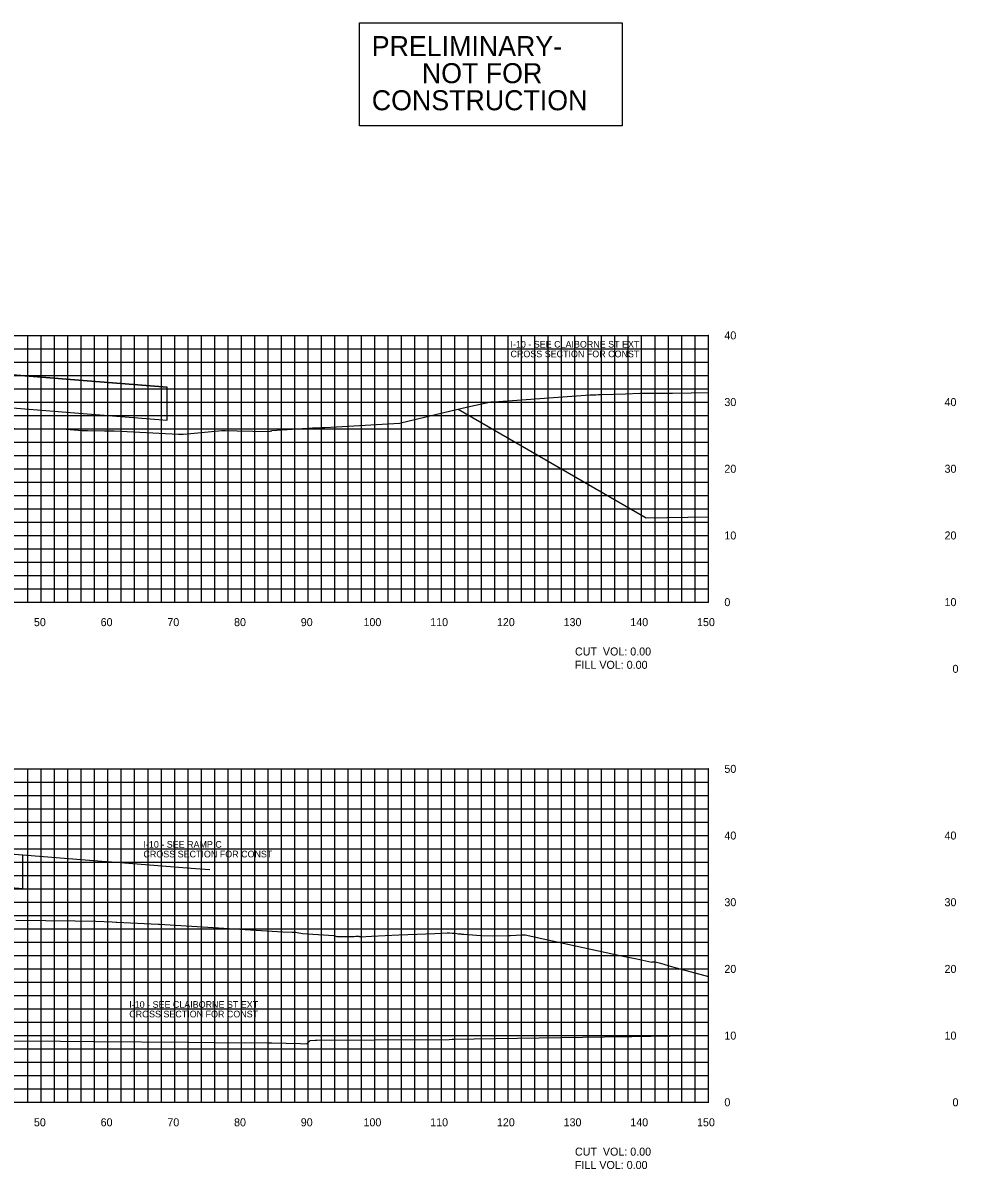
# Model space of a CAD drawing. Extents: x 1800880 to 1814006, y 250083 to 250560.
# Drawn here: x 1811858.3 to 1811998.4, y 250089.4 to 250261.3 of the extents above; entities that cross this region are included whole.
import ezdxf

# ---------------------------------------------------------------- set-up
doc = ezdxf.new("R2010")
doc.units = 0
for name, color, linetype in [('33', 7, 'Continuous'), ('AXIS', 7, 'Continuous'), ('CL-CNST', 7, 'Continuous'), ('DESIGN - DRAINAGE - Bridges', 7, 'Continuous'), ('DRAINAGETXT', 7, 'Continuous'), ('EPTEXT', 7, 'Continuous'), ('Level 32', 7, 'Continuous'), ('Level 46', 7, 'Continuous'), ('Level 62', 7, 'Continuous'), ('TOPO', 7, 'Continuous')]:
    doc.layers.add(name, color=color, linetype=linetype)

msp = doc.modelspace()

# ---------------------------------------------------------------- linework, layer by layer
at = {"layer": 'AXIS'}
msp.add_lwpolyline([(1811811, 250212.19), (1811812.25, 250212.09), (1811822.25, 250211.29), (1811834.25, 250210.33), (1811867.89, 250207.64), (1811879.89, 250206.68)], dxfattribs=at)
at = {"layer": 'CL-CNST'}
for points in [[(1811852.17, 250200.53), (1811861.88, 250200.43), (1811864.1, 250200.41), (1811865.35, 250200.32), (1811867.15, 250200.19), (1811867.94, 250200.18), (1811870.5, 250200.13), (1811871.44, 250200.11), (1811871.93, 250200.1), (1811881.59, 250199.61), (1811881.62, 250199.61), (1811881.77, 250199.6), (1811881.81, 250199.6), (1811881.93, 250199.6), (1811882.29, 250199.61), (1811883.41, 250199.71), (1811888.08, 250200.16), (1811888.14, 250200.16), (1811888.45, 250200.16), (1811888.61, 250200.16), (1811890.36, 250200.13), (1811895.05, 250200.03), (1811895.29, 250200.08), (1811895.41, 250200.11), (1811895.46, 250200.12), (1811895.49, 250200.13), (1811895.5, 250200.13), (1811895.52, 250200.14), (1811895.53, 250200.14), (1811895.53, 250200.14), (1811895.54, 250200.14), (1811895.54, 250200.14), (1811895.54, 250200.14), (1811895.55, 250200.14), (1811895.55, 250200.14), (1811895.55, 250200.14), (1811895.55, 250200.14), (1811895.56, 250200.14), (1811895.56, 250200.14), (1811895.56, 250200.14), (1811895.56, 250200.15), (1811895.56, 250200.15), (1811895.56, 250200.15), (1811901.65, 250200.55), (1811901.78, 250200.56), (1811901.79, 250200.56), (1811901.81, 250200.56), (1811901.84, 250200.56), (1811901.87, 250200.56), (1811901.91, 250200.57), (1811902.57, 250200.58), (1811902.79, 250200.59), (1811903.01, 250200.6), (1811903.49, 250200.63), (1811905.26, 250200.73), (1811914.69, 250201.27), (1811921.35, 250202.85), (1811924.94, 250203.7), (1811928.41, 250204.47), (1811928.86, 250204.47), (1811928.89, 250204.47), (1811943.29, 250205.52), (1811943.41, 250205.53), (1811943.6, 250205.54), (1811943.62, 250205.54), (1811943.98, 250205.54), (1811944.12, 250205.54), (1811944.54, 250205.55), (1811944.99, 250205.56), (1811948.59, 250205.68), (1811950.73, 250205.75), (1811951.53, 250205.76), (1811955.63, 250205.78), (1811958.4, 250205.81), (1811961, 250205.85)], [(1811857.17, 250126.75), (1811866.1, 250126.64), (1811869.16, 250126.61), (1811871.62, 250126.47), (1811872.21, 250126.44), (1811872.34, 250126.43), (1811878.53, 250126.13), (1811878.71, 250126.13), (1811897.2, 250125.01), (1811898.62, 250124.93), (1811898.66, 250124.93), (1811898.82, 250124.93), (1811899.17, 250124.92), (1811899.35, 250124.87), (1811900.18, 250124.73), (1811904.88, 250124.42), (1811905.31, 250124.3), (1811907.83, 250124.3), (1811907.9, 250124.3), (1811907.92, 250124.3), (1811908.14, 250124.35), (1811908.39, 250124.34), (1811908.4, 250124.34), (1811908.41, 250124.34), (1811908.42, 250124.34), (1811908.44, 250124.34), (1811908.46, 250124.34), (1811908.48, 250124.34), (1811908.53, 250124.33), (1811908.56, 250124.32), (1811908.6, 250124.32), (1811908.65, 250124.31), (1811908.72, 250124.29), (1811908.83, 250124.27), (1811908.85, 250124.26), (1811910.49, 250124.34), (1811914.6, 250124.52), (1811920.01, 250124.76), (1811921.83, 250124.82), (1811922.18, 250124.85), (1811922.59, 250124.81), (1811922.99, 250124.77), (1811923.28, 250124.74), (1811923.51, 250124.71), (1811923.69, 250124.69), (1811923.84, 250124.68), (1811923.96, 250124.67), (1811924.06, 250124.66), (1811924.15, 250124.65), (1811924.23, 250124.64), (1811924.29, 250124.63), (1811924.35, 250124.63), (1811925.66, 250124.54), (1811926.83, 250124.45), (1811928.68, 250124.38), (1811931.15, 250124.46), (1811931.32, 250124.45), (1811933.02, 250124.54), (1811933.35, 250124.53), (1811933.53, 250124.53), (1811936.51, 250123.89), (1811947.97, 250121.41), (1811948.48, 250121.3), (1811950.28, 250120.94), (1811952.54, 250120.46), (1811952.56, 250120.47), (1811953, 250120.47), (1811953.84, 250120.27), (1811955.13, 250119.9), (1811956.16, 250119.61), (1811961, 250118.3)]]:
    msp.add_lwpolyline(points, dxfattribs=at)
at = {"layer": 'DESIGN - DRAINAGE - Bridges'}
for p, q in [((1811961, 250174.43), (1811961, 250214.43)), ((1811961.06, 250214.43), (1811961, 250214.43)), ((1811961.06, 250204.43), (1811961, 250204.43)), ((1811961.06, 250194.43), (1811961, 250194.43)), ((1811961.06, 250184.43), (1811961, 250184.43)), ((1811661, 250174.43), (1811961, 250174.43)), ((1811861, 250174.37), (1811861, 250174.43)), ((1811871, 250174.37), (1811871, 250174.43)), ((1811881, 250174.37), (1811881, 250174.43)), ((1811891, 250174.37), (1811891, 250174.43)), ((1811901, 250174.37), (1811901, 250174.43)), ((1811911, 250174.37), (1811911, 250174.43)), ((1811921, 250174.37), (1811921, 250174.43)), ((1811931, 250174.37), (1811931, 250174.43)), ((1811941, 250174.37), (1811941, 250174.43)), ((1811951, 250174.37), (1811951, 250174.43)), ((1811961, 250174.37), (1811961, 250174.43)), ((1811961.06, 250174.43), (1811961, 250174.43)), ((1811961, 250099.43), (1811961, 250149.43)), ((1811961.06, 250149.43), (1811961, 250149.43)), ((1811961.06, 250139.43), (1811961, 250139.43)), ((1811961.06, 250129.43), (1811961, 250129.43)), ((1811961.06, 250119.43), (1811961, 250119.43)), ((1811961.06, 250109.43), (1811961, 250109.43)), ((1811661, 250099.43), (1811961, 250099.43)), ((1811861, 250099.37), (1811861, 250099.43)), ((1811871, 250099.37), (1811871, 250099.43)), ((1811881, 250099.37), (1811881, 250099.43)), ((1811891, 250099.37), (1811891, 250099.43)), ((1811901, 250099.37), (1811901, 250099.43)), ((1811911, 250099.37), (1811911, 250099.43)), ((1811921, 250099.37), (1811921, 250099.43)), ((1811931, 250099.37), (1811931, 250099.43)), ((1811941, 250099.37), (1811941, 250099.43)), ((1811951, 250099.37), (1811951, 250099.43)), ((1811961, 250099.37), (1811961, 250099.43)), ((1811961.06, 250099.43), (1811961, 250099.43))]:
    msp.add_line(p, q, dxfattribs=at)
at = {"layer": 'Level 32'}
msp.add_lwpolyline([(1811908.68, 250261.29), (1811948.08, 250261.29), (1811948.08, 250245.85), (1811908.68, 250245.85)], close=True, dxfattribs=at)
at = {"layer": 'Level 46'}
for p, q in [((1811661, 250214.43), (1811961, 250214.43)), ((1811859, 250174.43), (1811859, 250214.43)), ((1811861, 250174.43), (1811861, 250214.43)), ((1811863, 250174.43), (1811863, 250214.43)), ((1811865, 250174.43), (1811865, 250214.43)), ((1811867, 250174.43), (1811867, 250214.43)), ((1811869, 250174.43), (1811869, 250214.43)), ((1811871, 250174.43), (1811871, 250214.43)), ((1811873, 250174.43), (1811873, 250214.43)), ((1811875, 250174.43), (1811875, 250214.43)), ((1811877, 250174.43), (1811877, 250214.43)), ((1811879, 250174.43), (1811879, 250214.43)), ((1811881, 250174.43), (1811881, 250214.43)), ((1811883, 250174.43), (1811883, 250214.43)), ((1811885, 250174.43), (1811885, 250214.43)), ((1811887, 250174.43), (1811887, 250214.43)), ((1811889, 250174.43), (1811889, 250214.43)), ((1811891, 250174.43), (1811891, 250214.43)), ((1811893, 250174.43), (1811893, 250214.43)), ((1811895, 250174.43), (1811895, 250214.43)), ((1811897, 250174.43), (1811897, 250214.43)), ((1811899, 250174.43), (1811899, 250214.43)), ((1811901, 250174.43), (1811901, 250214.43)), ((1811903, 250174.43), (1811903, 250214.43)), ((1811905, 250174.43), (1811905, 250214.43)), ((1811907, 250174.43), (1811907, 250214.43)), ((1811909, 250174.43), (1811909, 250214.43)), ((1811911, 250174.43), (1811911, 250214.43)), ((1811913, 250174.43), (1811913, 250214.43)), ((1811915, 250174.43), (1811915, 250214.43)), ((1811917, 250174.43), (1811917, 250214.43)), ((1811919, 250174.43), (1811919, 250214.43)), ((1811921, 250174.43), (1811921, 250214.43)), ((1811923, 250174.43), (1811923, 250214.43)), ((1811925, 250174.43), (1811925, 250214.43)), ((1811927, 250174.43), (1811927, 250214.43)), ((1811929, 250174.43), (1811929, 250214.43)), ((1811931, 250174.43), (1811931, 250214.43)), ((1811933, 250174.43), (1811933, 250214.43)), ((1811935, 250174.43), (1811935, 250214.43)), ((1811937, 250174.43), (1811937, 250214.43)), ((1811939, 250174.43), (1811939, 250214.43)), ((1811941, 250174.43), (1811941, 250214.43)), ((1811943, 250174.43), (1811943, 250214.43)), ((1811945, 250174.43), (1811945, 250214.43)), ((1811947, 250174.43), (1811947, 250214.43)), ((1811949, 250174.43), (1811949, 250214.43)), ((1811951, 250174.43), (1811951, 250214.43)), ((1811953, 250174.43), (1811953, 250214.43)), ((1811955, 250174.43), (1811955, 250214.43)), ((1811957, 250174.43), (1811957, 250214.43)), ((1811959, 250174.43), (1811959, 250214.43)), ((1811961, 250174.43), (1811961, 250214.43)), ((1811661, 250212.43), (1811961, 250212.43)), ((1811661, 250210.43), (1811961, 250210.43)), ((1811661, 250208.43), (1811961, 250208.43)), ((1811661, 250206.43), (1811961, 250206.43)), ((1811661, 250204.43), (1811961, 250204.43)), ((1811661, 250202.43), (1811961, 250202.43)), ((1811661, 250200.43), (1811961, 250200.43)), ((1811661, 250198.43), (1811961, 250198.43)), ((1811661, 250196.43), (1811961, 250196.43)), ((1811661, 250194.43), (1811961, 250194.43)), ((1811661, 250192.43), (1811961, 250192.43)), ((1811661, 250190.43), (1811961, 250190.43)), ((1811661, 250188.43), (1811961, 250188.43)), ((1811661, 250186.43), (1811961, 250186.43)), ((1811661, 250184.43), (1811961, 250184.43)), ((1811661, 250182.43), (1811961, 250182.43)), ((1811661, 250180.43), (1811961, 250180.43)), ((1811661, 250178.43), (1811961, 250178.43)), ((1811661, 250176.43), (1811961, 250176.43)), ((1811661, 250174.43), (1811961, 250174.43)), ((1811661, 250149.43), (1811961, 250149.43)), ((1811859, 250099.43), (1811859, 250149.43)), ((1811861, 250099.43), (1811861, 250149.43)), ((1811863, 250099.43), (1811863, 250149.43)), ((1811865, 250099.43), (1811865, 250149.43)), ((1811867, 250099.43), (1811867, 250149.43)), ((1811869, 250099.43), (1811869, 250149.43)), ((1811871, 250099.43), (1811871, 250149.43)), ((1811873, 250099.43), (1811873, 250149.43)), ((1811875, 250099.43), (1811875, 250149.43)), ((1811877, 250099.43), (1811877, 250149.43)), ((1811879, 250099.43), (1811879, 250149.43)), ((1811881, 250099.43), (1811881, 250149.43)), ((1811883, 250099.43), (1811883, 250149.43)), ((1811885, 250099.43), (1811885, 250149.43)), ((1811887, 250099.43), (1811887, 250149.43)), ((1811889, 250099.43), (1811889, 250149.43)), ((1811891, 250099.43), (1811891, 250149.43)), ((1811893, 250099.43), (1811893, 250149.43)), ((1811895, 250099.43), (1811895, 250149.43)), ((1811897, 250099.43), (1811897, 250149.43)), ((1811899, 250099.43), (1811899, 250149.43)), ((1811901, 250099.43), (1811901, 250149.43)), ((1811903, 250099.43), (1811903, 250149.43)), ((1811905, 250099.43), (1811905, 250149.43)), ((1811907, 250099.43), (1811907, 250149.43)), ((1811909, 250099.43), (1811909, 250149.43)), ((1811911, 250099.43), (1811911, 250149.43)), ((1811913, 250099.43), (1811913, 250149.43)), ((1811915, 250099.43), (1811915, 250149.43)), ((1811917, 250099.43), (1811917, 250149.43)), ((1811919, 250099.43), (1811919, 250149.43)), ((1811921, 250099.43), (1811921, 250149.43)), ((1811923, 250099.43), (1811923, 250149.43)), ((1811925, 250099.43), (1811925, 250149.43)), ((1811927, 250099.43), (1811927, 250149.43)), ((1811929, 250099.43), (1811929, 250149.43)), ((1811931, 250099.43), (1811931, 250149.43)), ((1811933, 250099.43), (1811933, 250149.43)), ((1811935, 250099.43), (1811935, 250149.43)), ((1811937, 250099.43), (1811937, 250149.43)), ((1811939, 250099.43), (1811939, 250149.43)), ((1811941, 250099.43), (1811941, 250149.43)), ((1811943, 250099.43), (1811943, 250149.43)), ((1811945, 250099.43), (1811945, 250149.43)), ((1811947, 250099.43), (1811947, 250149.43)), ((1811949, 250099.43), (1811949, 250149.43)), ((1811951, 250099.43), (1811951, 250149.43)), ((1811953, 250099.43), (1811953, 250149.43)), ((1811955, 250099.43), (1811955, 250149.43)), ((1811957, 250099.43), (1811957, 250149.43)), ((1811959, 250099.43), (1811959, 250149.43)), ((1811961, 250099.43), (1811961, 250149.43)), ((1811661, 250147.43), (1811961, 250147.43)), ((1811661, 250145.43), (1811961, 250145.43)), ((1811661, 250143.43), (1811961, 250143.43)), ((1811661, 250141.43), (1811961, 250141.43)), ((1811661, 250139.43), (1811961, 250139.43)), ((1811661, 250137.43), (1811961, 250137.43)), ((1811661, 250135.43), (1811961, 250135.43)), ((1811661, 250133.43), (1811961, 250133.43)), ((1811661, 250131.43), (1811961, 250131.43)), ((1811661, 250129.43), (1811961, 250129.43)), ((1811661, 250127.43), (1811961, 250127.43)), ((1811661, 250125.43), (1811961, 250125.43)), ((1811661, 250123.43), (1811961, 250123.43)), ((1811661, 250121.43), (1811961, 250121.43)), ((1811661, 250119.43), (1811961, 250119.43)), ((1811661, 250117.43), (1811961, 250117.43)), ((1811661, 250115.43), (1811961, 250115.43)), ((1811661, 250113.43), (1811961, 250113.43)), ((1811661, 250111.43), (1811961, 250111.43)), ((1811661, 250109.43), (1811961, 250109.43)), ((1811661, 250107.43), (1811961, 250107.43)), ((1811661, 250105.43), (1811961, 250105.43)), ((1811661, 250103.43), (1811961, 250103.43)), ((1811661, 250101.43), (1811961, 250101.43)), ((1811661, 250099.43), (1811961, 250099.43))]:
    msp.add_line(p, q, dxfattribs=at)
at = {"layer": 'Level 62'}
for points in [[(1811923.49, 250203.35), (1811951.68, 250187.09), (1811961, 250187.24)], [(1811858.25, 250136.52), (1811870.06, 250135.6), (1811872.24, 250135.43), (1811884.1, 250134.5), (1811886.29, 250134.33)], [(1811842.4, 250108.76), (1811863.88, 250108.58), (1811868.98, 250108.54), (1811883.12, 250108.45), (1811886.94, 250108.42), (1811894.92, 250108.37), (1811895.55, 250108.35), (1811899.86, 250108.25), (1811900.81, 250108.22), (1811900.91, 250108.32), (1811901.3, 250108.72), (1811902.04, 250108.73), (1811902.28, 250108.73), (1811902.28, 250108.73), (1811902.29, 250108.73), (1811910.96, 250108.79), (1811922.13, 250108.87), (1811922.58, 250108.88), (1811922.93, 250108.88), (1811923.02, 250108.88), (1811925.87, 250108.93), (1811948.7, 250109.28), (1811949.51, 250109.29), (1811961, 250109.49)]]:
    msp.add_lwpolyline(points, dxfattribs=at)
at = {"layer": 'TOPO'}
for points in [[(1811867.89, 250202.68), (1811879.89, 250201.72), (1811879.89, 250206.68), (1811867.89, 250207.64), (1811834.25, 250210.33), (1811822.25, 250211.29), (1811812.25, 250212.09), (1811811, 250212.19), (1811811, 250207.23), (1811812.25, 250207.13), (1811822.25, 250206.33), (1811834.25, 250205.37)], [(1811846.25, 250132.47), (1811858.25, 250131.51), (1811858.25, 250136.47), (1811846.25, 250137.43), (1811834.25, 250138.39), (1811822.25, 250139.35), (1811812.25, 250140.15), (1811811, 250140.25), (1811811, 250135.29), (1811812.25, 250135.19), (1811822.25, 250134.39), (1811834.25, 250133.43)]]:
    msp.add_lwpolyline(points, close=True, dxfattribs=at)

# ---------------------------------------------------------------- texts
for s, p in [('50', (1811859.9, 250170.83)), ('60', (1811869.9, 250170.83)), ('70', (1811879.9, 250170.83)), ('80', (1811889.9, 250170.83)), ('90', (1811899.9, 250170.83)), ('100', (1811909.3, 250170.83)), ('110', (1811919.3, 250170.83)), ('120', (1811929.3, 250170.83)), ('130', (1811939.3, 250170.83)), ('140', (1811949.3, 250170.83)), ('150', (1811959.3, 250170.83)), ('50', (1811859.9, 250095.83)), ('60', (1811869.9, 250095.83)), ('70', (1811879.9, 250095.83)), ('80', (1811889.9, 250095.83)), ('90', (1811899.9, 250095.83)), ('100', (1811909.3, 250095.83)), ('110', (1811919.3, 250095.83)), ('120', (1811929.3, 250095.83)), ('130', (1811939.3, 250095.83)), ('140', (1811949.3, 250095.83)), ('150', (1811959.3, 250095.83))]:
    msp.add_text(s, height=1.2).set_placement(p)
at = {"layer": '33'}
for s, p in [('40', (1811963.4, 250213.83)), ('30', (1811963.4, 250203.83)), ('40', (1811996.4, 250203.83)), ('20', (1811963.4, 250193.83)), ('30', (1811996.4, 250193.83)), ('10', (1811963.4, 250183.83)), ('20', (1811996.4, 250183.83)), ('0', (1811963.4, 250173.83)), ('10', (1811996.4, 250173.83)), ('0', (1811997.6, 250163.83)), ('50', (1811963.4, 250148.83)), ('40', (1811963.4, 250138.83)), ('40', (1811996.4, 250138.83)), ('30', (1811963.4, 250128.83)), ('30', (1811996.4, 250128.83)), ('20', (1811963.4, 250118.83)), ('20', (1811996.4, 250118.83)), ('10', (1811963.4, 250108.83)), ('10', (1811996.4, 250108.83)), ('0', (1811963.4, 250098.83)), ('0', (1811997.6, 250098.83))]:
    msp.add_text(s, height=1.2, dxfattribs=at).set_placement(p)
at = {"layer": 'DRAINAGETXT'}
for s, p in [('CUT  VOL: 0.00', (1811941, 250166.43)), ('FILL VOL: 0.00', (1811941, 250164.43)), ('CUT  VOL: 0.00', (1811941, 250091.43)), ('FILL VOL: 0.00', (1811941, 250089.43))]:
    msp.add_text(s, height=1.2, dxfattribs=at).set_placement(p)
at = {"layer": 'EPTEXT'}
for s, p in [('I-10 - SEE CLAIBORNE ST EXT', (1811931.34, 250212.6)), ('CROSS SECTION FOR CONST', (1811931.34, 250211.15)), ('I-10 - SEE RAMP C', (1811876.32, 250137.6)), ('CROSS SECTION FOR CONST ', (1811876.32, 250136.15)), ('I-10 - SEE CLAIBORNE ST EXT', (1811874.19, 250113.6)), ('CROSS SECTION FOR CONST ', (1811874.19, 250112.16))]:
    msp.add_text(s, height=1, dxfattribs=at).set_placement(p)
at = {"layer": 'Level 32'}
for s, p in [('PRELIMINARY-', (1811910.54, 250256.31)), ('NOT FOR', (1811918.05, 250252.25)), ('CONSTRUCTION', (1811910.55, 250248.19))]:
    msp.add_text(s, height=3, dxfattribs=at).set_placement(p)

doc.saveas('drawing.dxf')
